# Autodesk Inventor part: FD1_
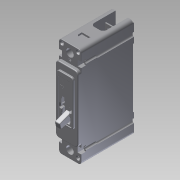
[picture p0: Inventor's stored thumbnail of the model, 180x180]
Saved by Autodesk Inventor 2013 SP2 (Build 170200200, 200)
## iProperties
Created: 2014-08
Part Number: FD1_
Material: Generic
Document SubType Name: Modeling
Designer: DM/JS
Density: 1 g/cm^3
Description: TYPE FD THERMAL MAGNETIC CIRCUIT BREAKERS SINGLE POLE, SERIES C
Translation Standard: STEP AP214IS
FileName: Y:\ECO-062745\WIP\New\FD1_.stp
PreProcessor: Autodesk Inventor 2012
PostProcessor: Build: 219, Release: 2012 SP2 - Date: Fri 04/27/2012
Sent Units: inch
Uncertainty: 0.00039370078740199997
MXEDIT: false
MXINVTNRV: INV Versioned Component|FD1_|003.0
Author: DM/JS
Revision Number: 003
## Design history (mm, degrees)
node "FD1_"
node "L1"
node "L2"
body "Solid1"
node "Base1"
